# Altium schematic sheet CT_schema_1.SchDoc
size 743 x 512 mm
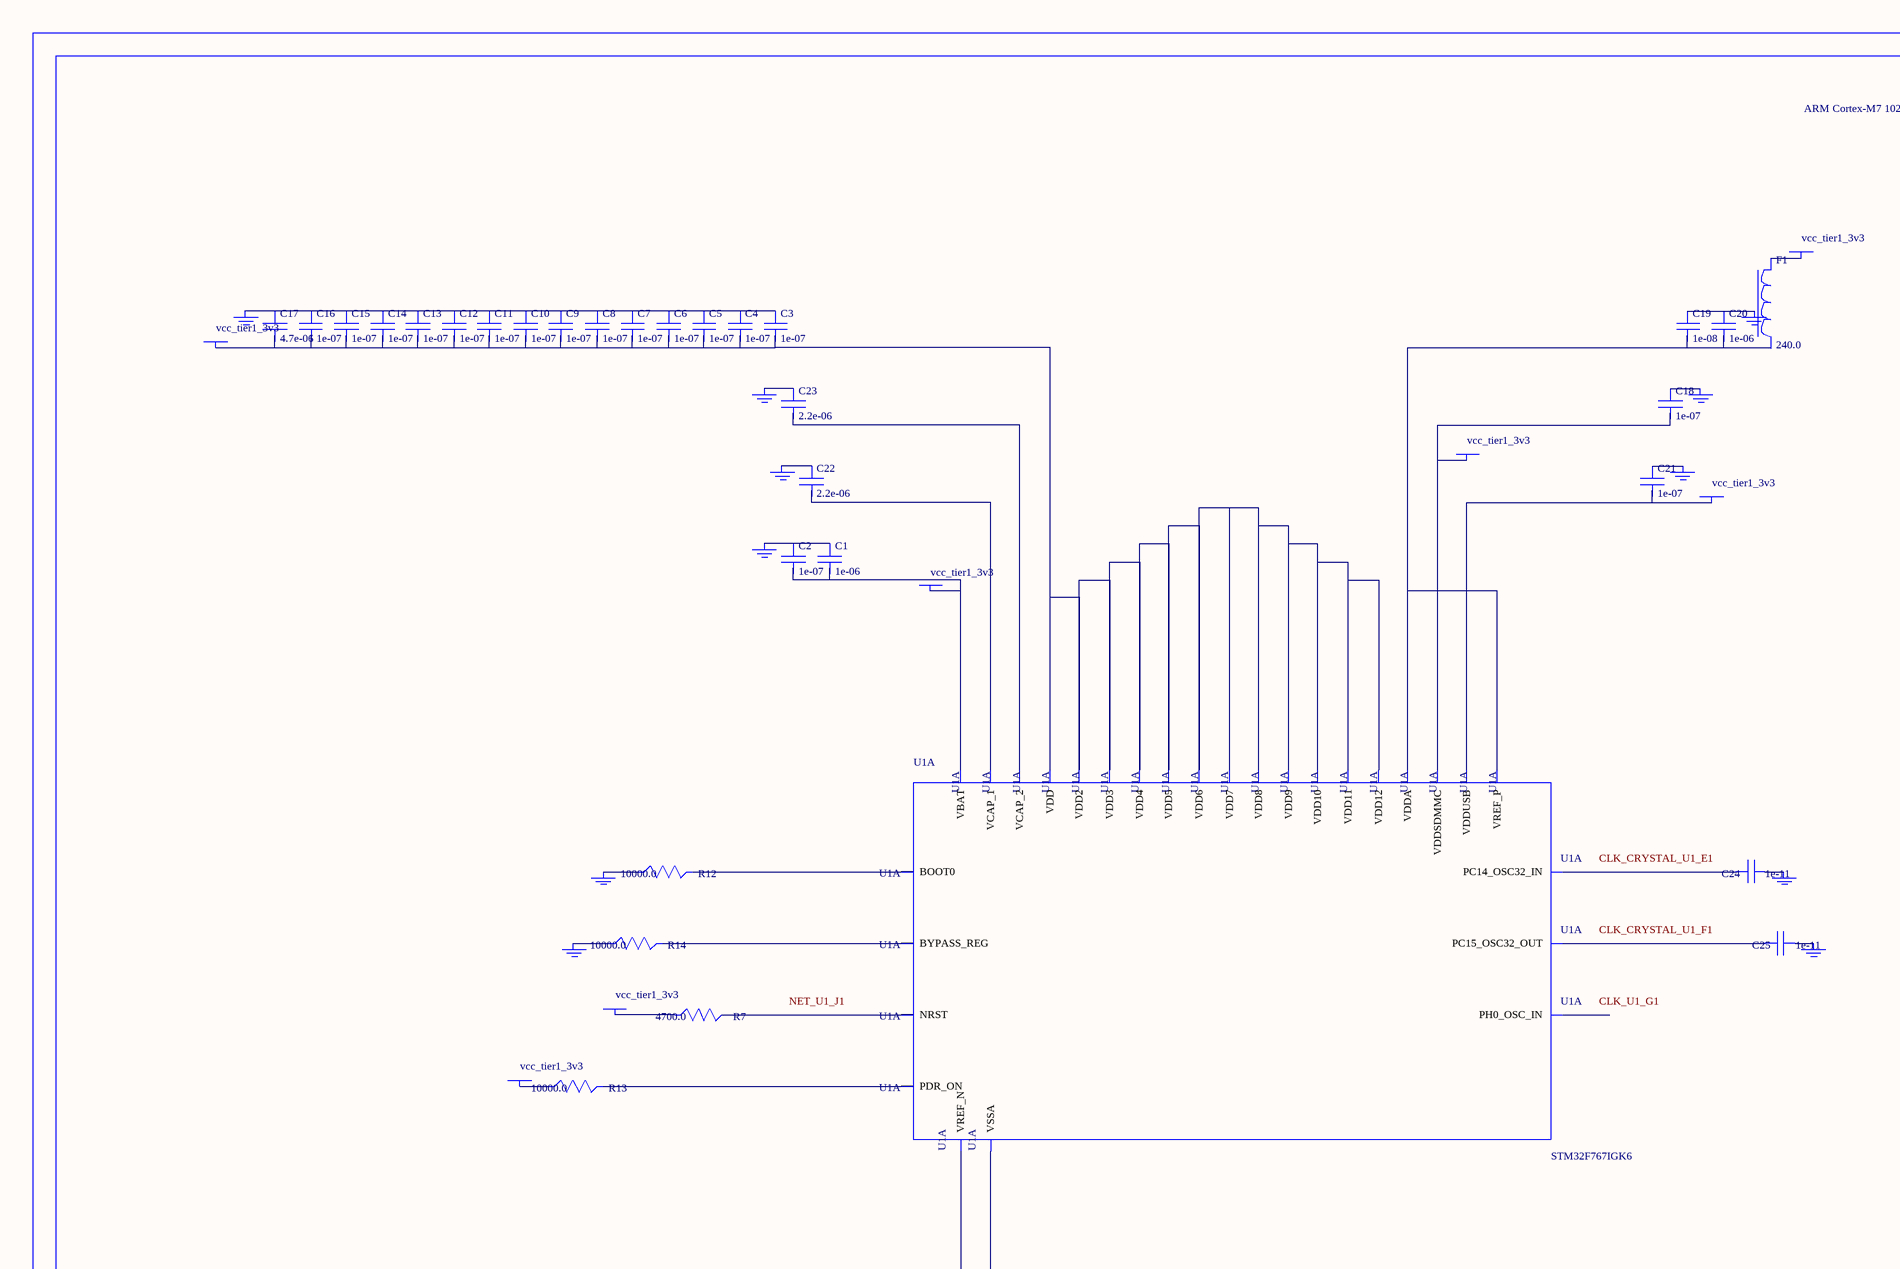
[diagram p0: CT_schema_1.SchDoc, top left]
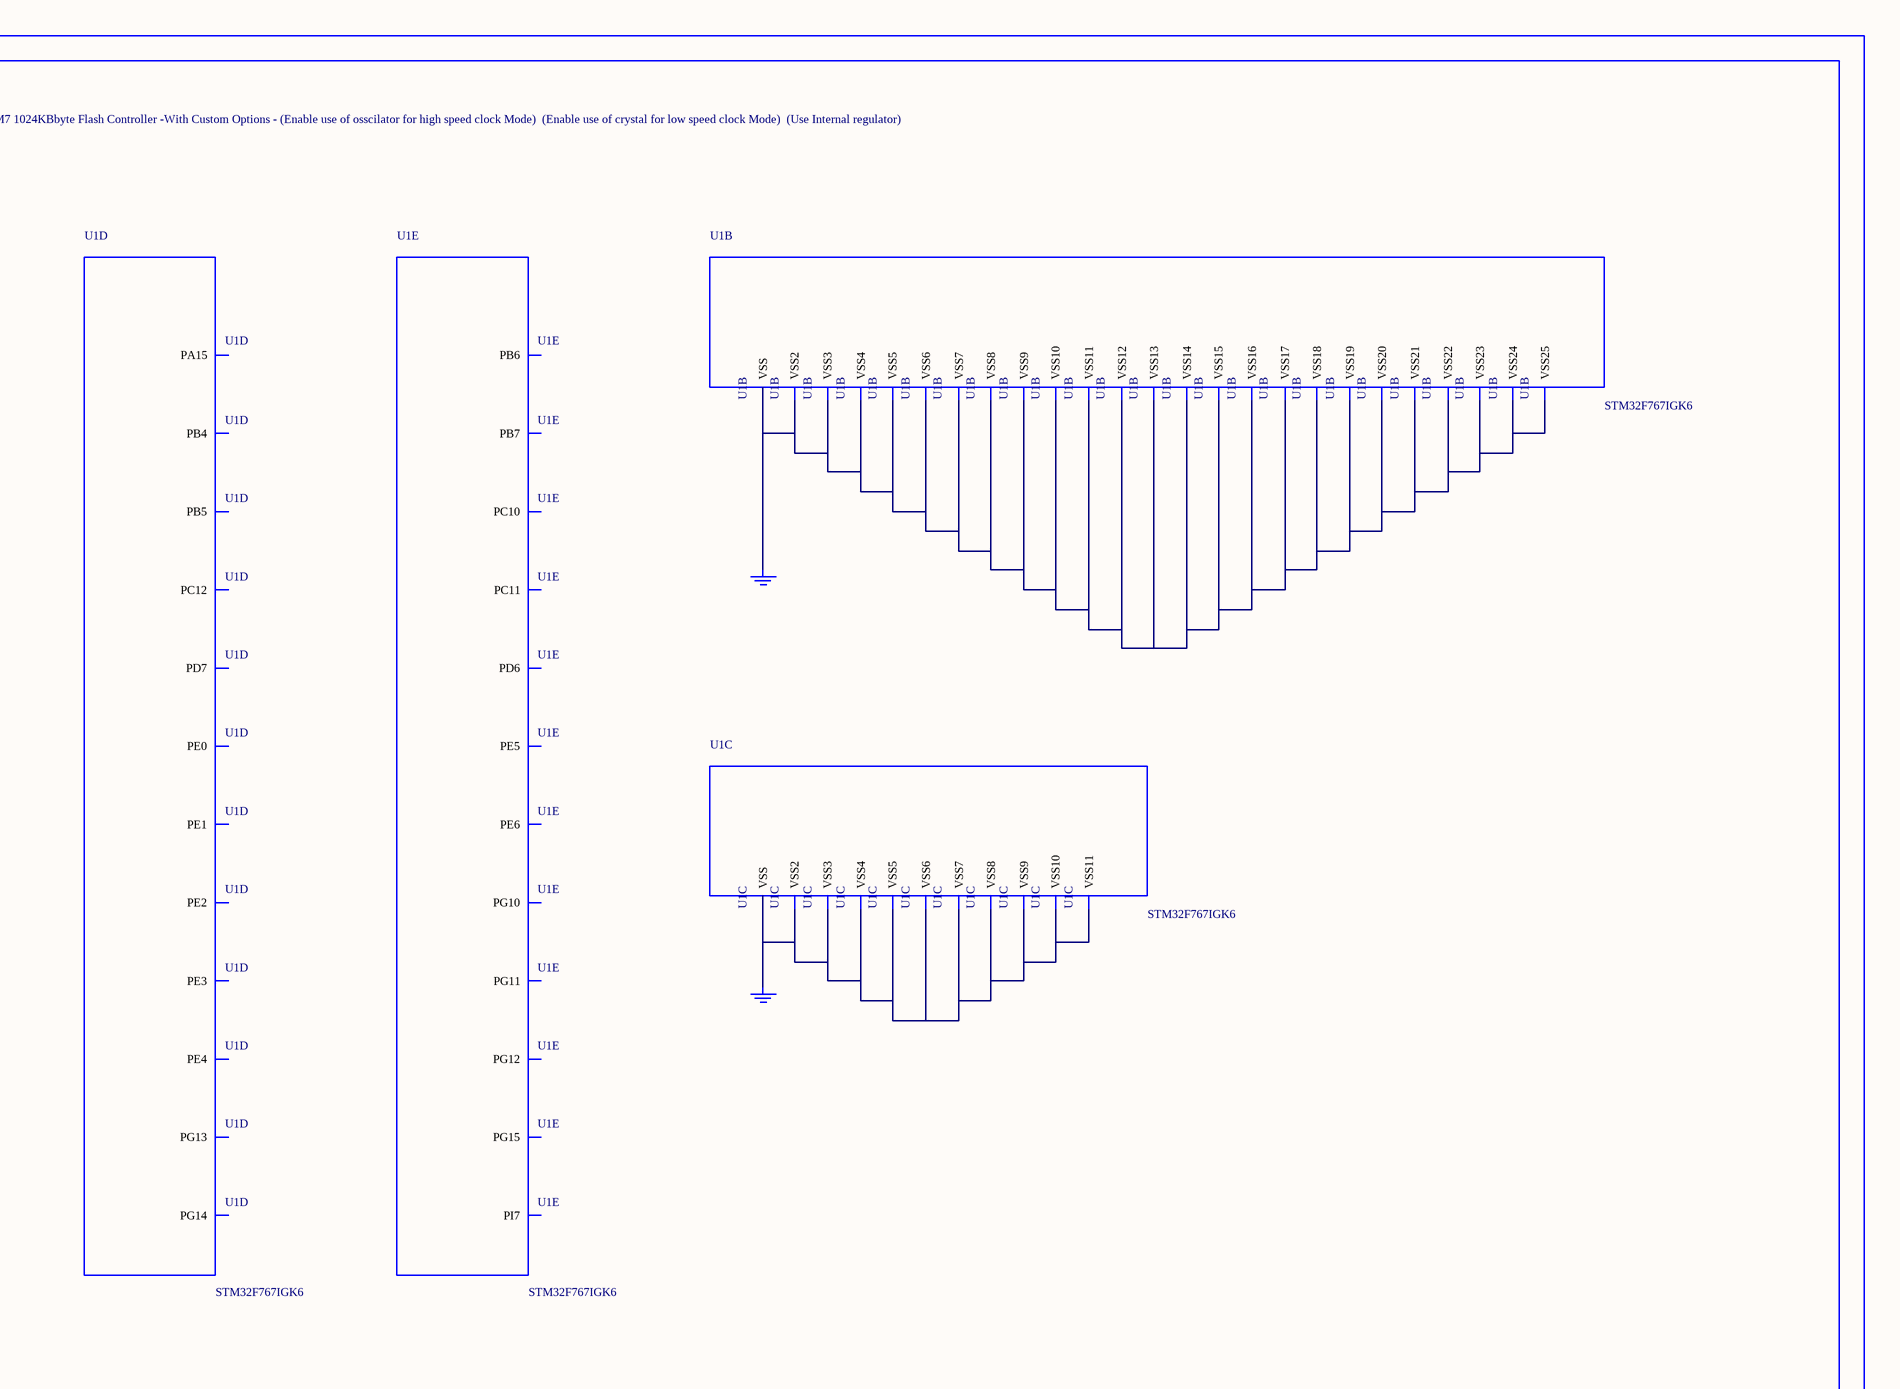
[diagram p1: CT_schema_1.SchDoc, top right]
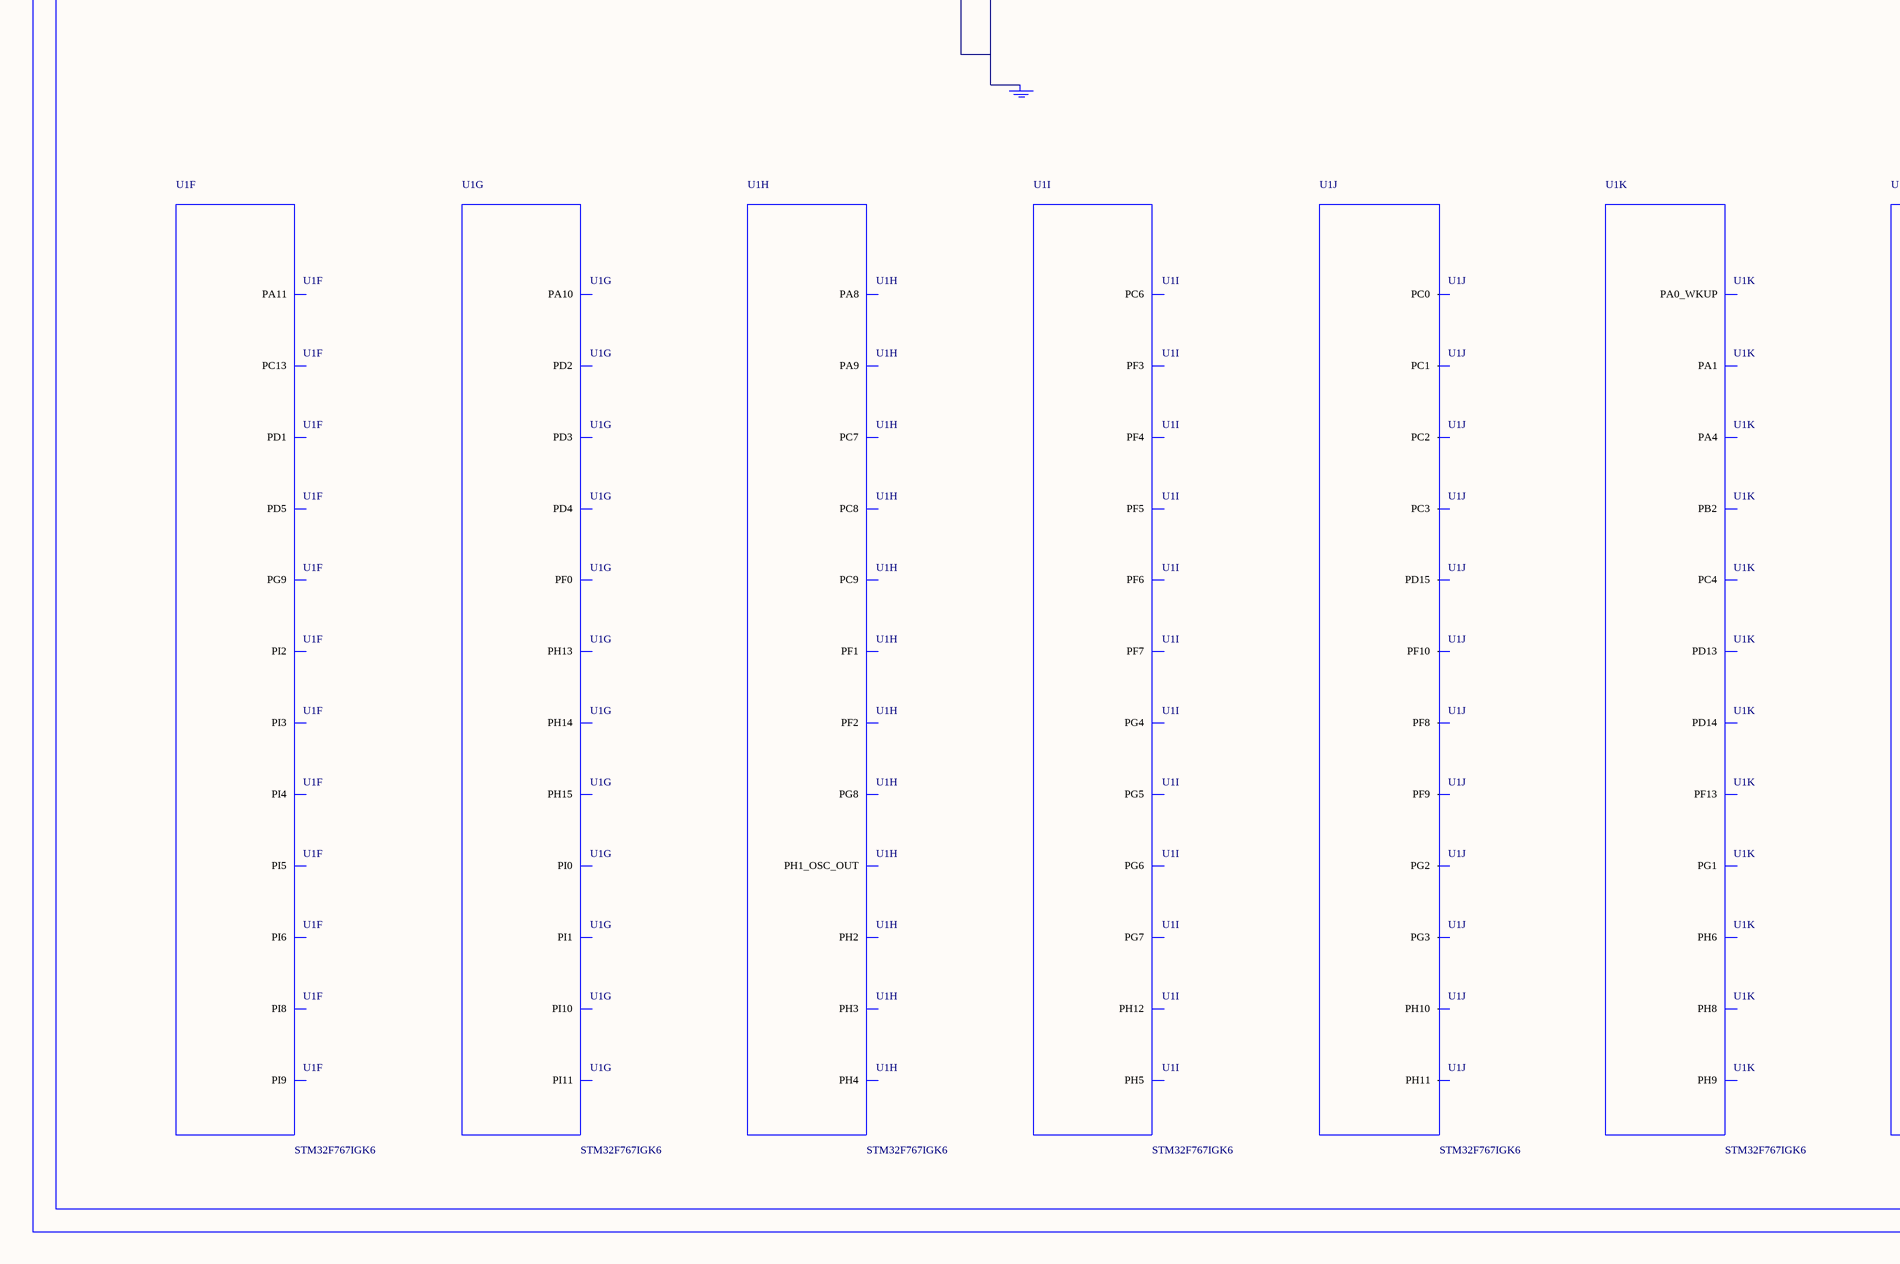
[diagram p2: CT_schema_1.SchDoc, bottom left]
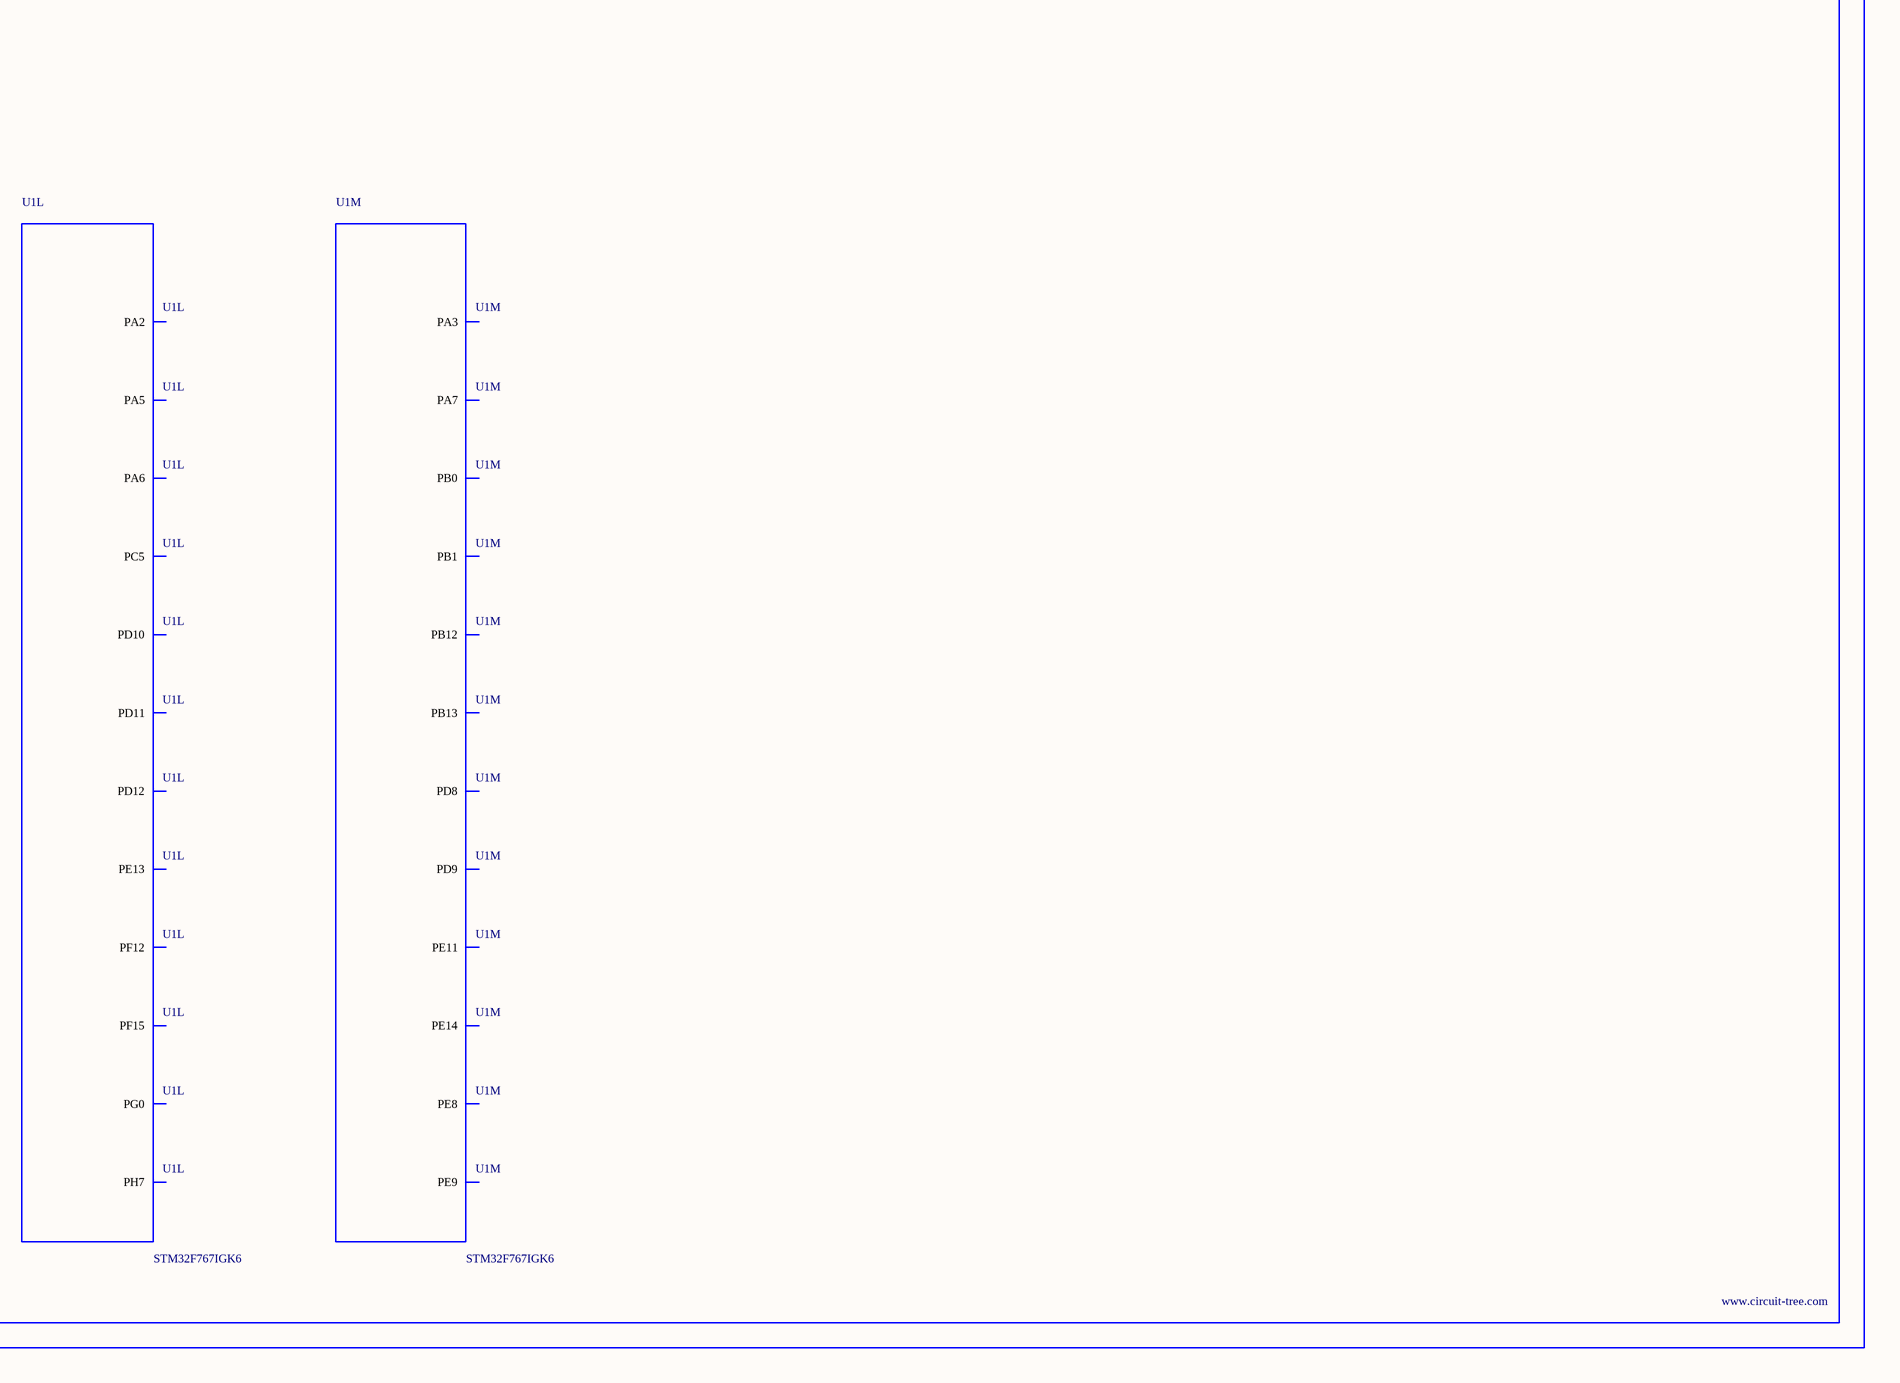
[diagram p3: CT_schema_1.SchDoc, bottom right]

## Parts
BORDER0  (no value)
C1  1e-06  [C0603]
C2  1e-07  [C0603]
C3  1e-07  [C0603]
C4  1e-07  [C0603]
C5  1e-07  [C0603]
C6  1e-07  [C0603]
C7  1e-07  [C0603]
C8  1e-07  [C0603]
C9  1e-07  [C0603]
C10  1e-07  [C0603]
C11  1e-07  [C0603]
C12  1e-07  [C0603]
C13  1e-07  [C0603]
C14  1e-07  [C0603]
C15  1e-07  [C0603]
C16  1e-07  [C0603]
C17  4.7e-06  [C0603]
C18  1e-07  [C0603]
C19  1e-08  [C0603]
C20  1e-06  [C0603]
C21  1e-07  [C0603]
C22  2.2e-06  [C0603]
C23  2.2e-06  [C0603]
C24  1e-11  [C0402]
C25  1e-11  [C0402]
F1  240.0  [L0603]
GND_INSTANCE_0_0  (no value)
GND_INSTANCE_0_1  (no value)
GND_INSTANCE_0_2  (no value)
GND_INSTANCE_0_3  (no value)
GND_INSTANCE_0_4  (no value)
GND_INSTANCE_0_5  (no value)
GND_INSTANCE_0_6  (no value)
GND_INSTANCE_0_7  (no value)
GND_INSTANCE_0_8  (no value)
GND_INSTANCE_0_9  (no value)
GND_INSTANCE_0_10  (no value)
GND_INSTANCE_0_11  (no value)
GND_INSTANCE_0_12  (no value)
GND_INSTANCE_0_13  (no value)
POWER_INSTANCE_0_0  vcc_tier1_3v3
POWER_INSTANCE_0_1  vcc_tier1_3v3
POWER_INSTANCE_0_2  vcc_tier1_3v3
POWER_INSTANCE_0_3  vcc_tier1_3v3
POWER_INSTANCE_0_4  vcc_tier1_3v3
POWER_INSTANCE_0_5  vcc_tier1_3v3
POWER_INSTANCE_0_6  vcc_tier1_3v3
R7  4700.0  [R0603]
R12  10000.0  [R0603]
R13  10000.0  [R0603]
R14  10000.0  [R0603]
U1  STM32F767IGK6  [UFBGA176_25]  (parts A,B,C,D,E,F,G,H,I,J,K,L,M of 16)

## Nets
NetC1_1: C1.1 C2.1 GND_INSTANCE_0_0.0(GND)
NetC1_2: C1.2 C2.2 POWER_INSTANCE_0_0.0(PWR) U1.C1(VBAT)
NetC3_1: C3.1 C4.1 C5.1 C6.1 C7.1 C8.1 C9.1 C10.1 C11.1 C12.1 C13.1 C14.1 C15.1 C16.1 C17.1 GND_INSTANCE_0_2.0(GND)
NetC3_2: C3.2 C4.2 C5.2 C6.2 C7.2 C8.2 C9.2 C10.2 C11.2 C12.2 C13.2 C14.2 C15.2 C16.2 C17.2 POWER_INSTANCE_0_2.0(PWR) U1.C5(VDD) U1.C7(VDD2) U1.C9(VDD3) U1.F3(VDD4) U1.G3(VDD6) U1.G13(VDD5) U1.J12(VDD7) U1.J13(VDD8) U1.K4(VDD9) U1.N8(VDD11) U1.N9(VDD12) U1.N10(VDD10)
NetC18_1: C18.1 GND_INSTANCE_0_4.0(GND)
NetC18_2: C18.2 POWER_INSTANCE_0_3.0(PWR) U1.C8(VDDSDMMC)
NetC19_1: C19.1 C20.1 GND_INSTANCE_0_1.0(GND)
NetC19_2: C19.2 C20.2 U1.P1(VREF_P) U1.R1(VDDA)
NetC21_1: C21.1 GND_INSTANCE_0_5.0(GND)
NetC21_2: C21.2 POWER_INSTANCE_0_5.0(PWR) U1.H13(VDDUSB)
NetC22_1: C22.1 GND_INSTANCE_0_7.0(GND)
NetC22_2: C22.2 U1.M10(VCAP_1)
NetC23_1: C23.1 GND_INSTANCE_0_8.0(GND)
NetC23_2: C23.2 U1.F13(VCAP_2)
NetC24_1: C24.1 GND_INSTANCE_0_9.0(GND)
NetC24_2: C24.2 U1.E1(PC14_OSC32_IN)
NetC25_1: C25.1 GND_INSTANCE_0_10.0(GND)
NetC25_2: C25.2 U1.F1(PC15_OSC32_OUT)
NetF1_1: F1.1 POWER_INSTANCE_0_1.0(PWR)
NetGND_INSTANCE_0_3_0: GND_INSTANCE_0_3.0(GND) R12.1
NetGND_INSTANCE_0_6_0: GND_INSTANCE_0_6.0(GND) R14.1
NetGND_INSTANCE_0_11_0: GND_INSTANCE_0_11.0(GND) U1.M1(VSSA) U1.N1(VREF_N)
NetGND_INSTANCE_0_12_0: GND_INSTANCE_0_12.0(GND) U1.D5(VSS) U1.D7(VSS2) U1.D8(VSS3) U1.D9(VSS4) U1.F2(VSS7) U1.F6(VSS8) U1.F7(VSS9) U1.F8(VSS10) U1.F9(VSS11) U1.F10(VSS5) U1.F12(VSS6) U1.G2(VSS14) U1.G6(VSS15) U1.G7(VSS16) U1.G8(VSS17) U1.G9(VSS18) U1.G10(VSS12) U1.G12(VSS13) U1.H6(VSS21) U1.H7(VSS22) U1.H8(VSS23) U1.H9(VSS24) U1.H10(VSS19) U1.H12(VSS20) U1.J10(VSS25)
NetGND_INSTANCE_0_13_0: GND_INSTANCE_0_13.0(GND) U1.J6(VSS) U1.J7(VSS2) U1.J8(VSS3) U1.J9(VSS4) U1.K6(VSS6) U1.K7(VSS7) U1.K8(VSS8) U1.K9(VSS9) U1.K10(VSS5) U1.M8(VSS10) U1.M9(VSS11)
NetPOWER_INSTANCE_0_4_0: POWER_INSTANCE_0_4.0(PWR) R13.1
NetPOWER_INSTANCE_0_6_0: POWER_INSTANCE_0_6.0(PWR) R7.1
NetR7_2: R7.2 U1.J1(NRST)
NetR12_2: R12.2 U1.D6(BOOT0)
NetR13_2: R13.2 U1.C6(PDR_ON)
NetR14_2: R14.2 U1.L4(BYPASS_REG)

Not connected (* = marked no-connect by the designer): F1 2; U1 A1(PE3) A2(PE2) A3(PE1) A4(PE0) A6(PB5) A7(PG14) A8(PG13) A9(PB4) A11(PD7) A12(PC12) A13(PA15) B1(PE4) B2(PE5) B3(PE6) B5(PB7) B6(PB6) B7(PG15) B8(PG12) B9(PG11) B10(PG10) B11(PD6) B13(PC11) B14(PC10) C2(PI7) C3(PI6) C4(PI5) C10(PG9) C11(PD5) C12(PD1) C13(PI3) C14(PI2) C15(PA11) D1(PC13) D2(PI8) D3(PI9) D4(PI4) D10(PD4) D11(PD3) D12(PD2) D13(PH15) D14(PI1) D15(PA10) E2(PF0) E3(PI10) E4(PI11) E12(PH13) E13(PH14) E14(PI0) E15(PA9) F4(PH2) F14(PC9) F15(PA8) G1(PH0_OSC_IN) G4(PH3) G14(PC8) G15(PC7) H1(PH1_OSC_OUT) H2(PF2) H3(PF1) H4(PH4) H14(PG8) H15(PC6) J2(PF3) J3(PF4) J4(PH5) J14(PG7) J15(PG6) K1(PF7) K2(PF6) K3(PF5) K12(PH12) K13(PG5) K14(PG4) K15(PG3) L1(PF10) L2(PF9) L3(PF8) L12(PH11) L13(PH10) L14(PD15) L15(PG2) M2(PC0) M3(PC1) M4(PC2) M5(PC3) M6(PB2) M7(PG1) M11(PH6) M12(PH8) M13(PH9) M14(PD14) M15(PD13) N2(PA1) N3(PA0_WKUP) N4(PA4) N5(PC4) N6(PF13) N7(PG0) N11(PE13) N12(PH7) N13(PD12) N14(PD11) N15(PD10) P2(PA2) P3(PA6) P4(PA5) P5(PC5) P6(PF12) P7(PF15) P8(PE8) P9(PE9) P10(PE11) P11(PE14) P12(PB12) P13(PB13) P14(PD9) P15(PD8) R2(PA3) R3(PA7) R4(PB1) R5(PB0)

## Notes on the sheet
- Labels drawn without touching a wire or pin: CLK_CRYSTAL_U1_E1, CLK_CRYSTAL_U1_F1, CLK_U1_G1, NET_U1_J1

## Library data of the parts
BORDER0 = BORDER_PAGE0
C1 C20 = C0603C105K3RACTU
C2-C16 C18 C21 = 06035C104K4Z2A
C17 = GRM188R6YA475KE15D
C19 = 06035C103K4Z2A
C22 C23 = C0603C225K8RACTU
C24 C25 = C0402C100K3GACTU
F1 = Z0603C241ASMST
GND_INSTANCE_0_0-GND_INSTANCE_0_13 = GND
POWER_INSTANCE_0_0-POWER_INSTANCE_0_6 = PWR
R7 = RC0603JR-074K7L
R12-R14 = RC0603JR-0710KL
